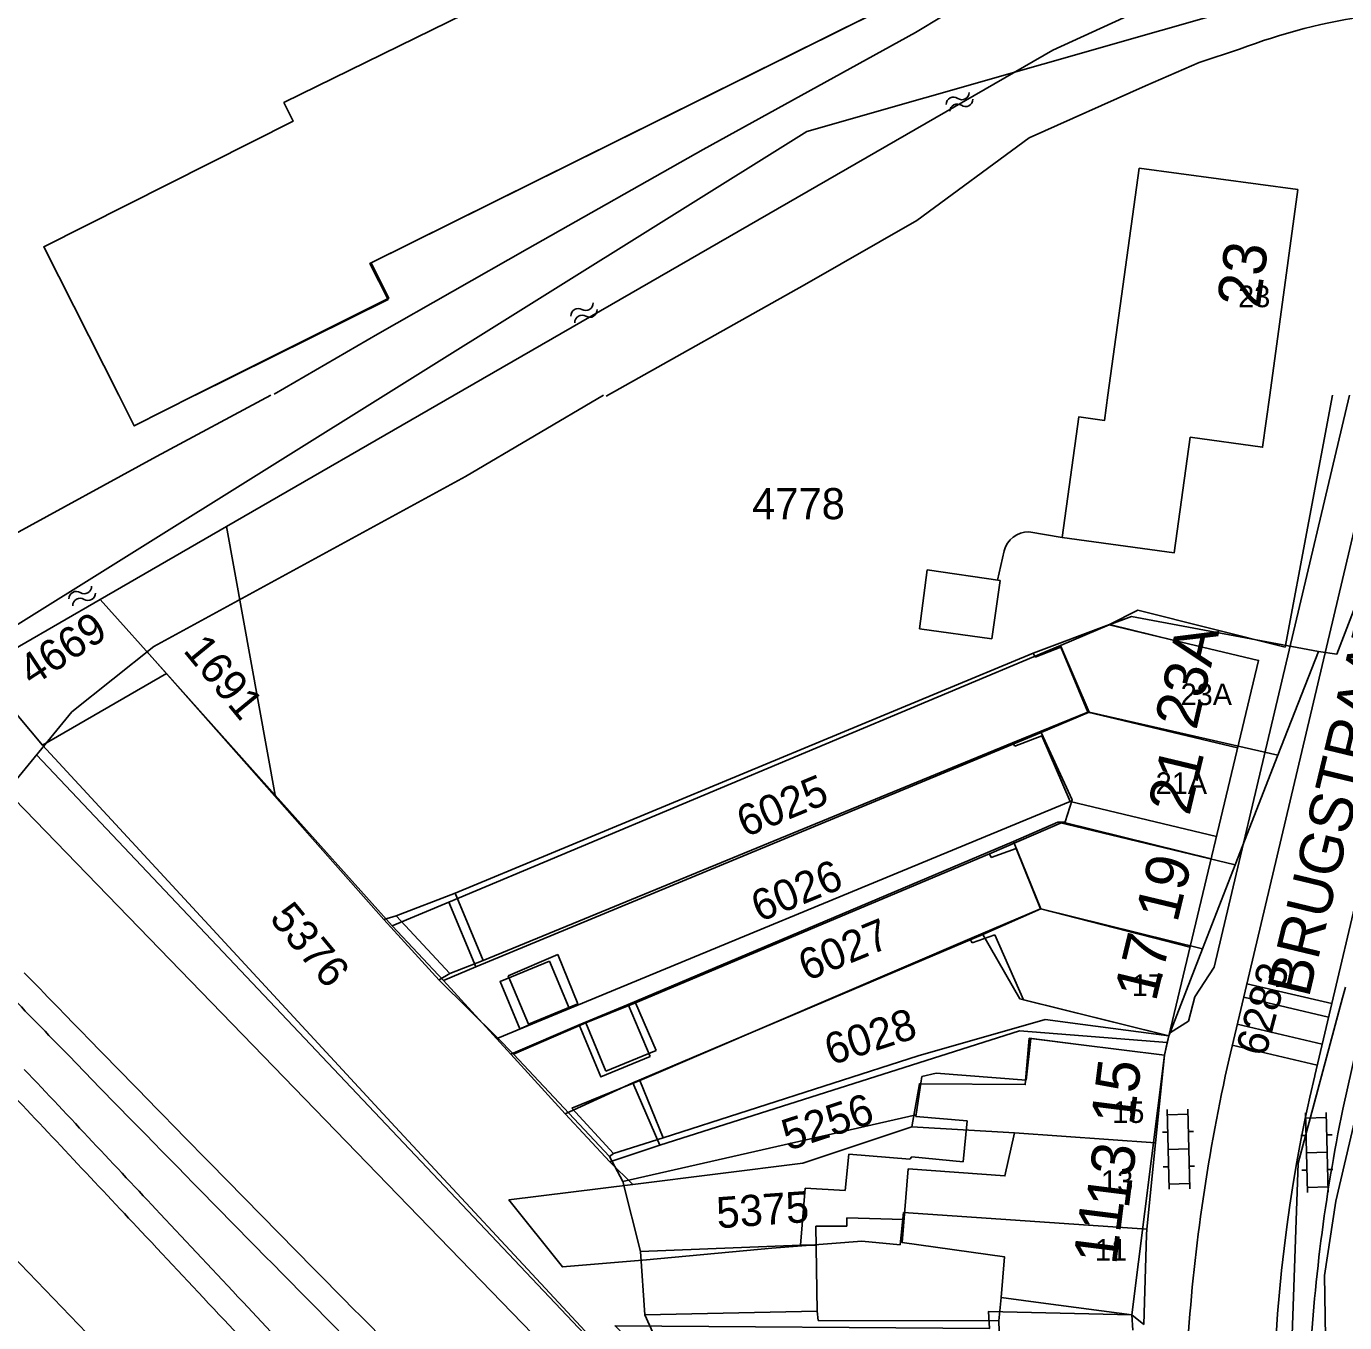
# Model space of a CAD drawing. Extents: x 148816 to 151297, y 399515 to 402500.
# Drawn here: x 149846 to 149922.2, y 399946.4 to 400021.3 of the extents above; entities that cross this region are included whole.
import ezdxf

# ---------------------------------------------------------------- set-up
doc = ezdxf.new("R2010")
doc.units = 0
for name, color, linetype in [('B01 Hoofdgebouw  [D] Norm', 7, 'Continuous'), ('B01 Hoofdgebouw  [T] Norm', 7, 'Continuous'), ('B01 hoofgebouw', 7, 'Continuous'), ('B02 Bijgebouw  [D] Norm', 7, 'Continuous'), ('B02 Bijgebouw  [T] Norm', 7, 'Continuous'), ('B07 Tussenmuur  [D] Norm', 7, 'Continuous'), ('G01 perceelsgrens', 7, 'Continuous'), ('G02 sectiegrens', 7, 'Continuous'), ('Q01 Spoorrail  [D] Norm', 7, 'Continuous'), ('Q21 Lichtmast  Gem', 7, 'Continuous'), ('S02 Open verharding  Norm', 7, 'Continuous'), ('S05 Water  Norm', 7, 'Continuous'), ('T04 Haag heg  [D] Gem', 7, 'Continuous'), ('T09 Insteek water  [T] Norm', 7, 'Continuous'), ('V00 Kant verharding algemeen  [T] Norm', 7, 'Continuous'), ('Z01 perceelnummer', 7, 'Continuous'), ('Z02 huisnummer', 7, 'Continuous'), ('Z02 Huisnummer  [Tekst] Norm', 7, 'Continuous'), ('Z06 straatnaam', 7, 'Continuous')]:
    doc.layers.add(name, color=color, linetype=linetype)

msp = doc.modelspace()

# ---------------------------------------------------------------- linework, layer by layer
at = {"layer": 'B01 Hoofdgebouw  [D] Norm'}
for p, q in [((149902.132, 399989.308), (149902.517, 399991.014)), ((149898.07, 399989.917), (149897.615, 399986.509)), ((149902.289, 399989.285), (149898.07, 399989.917)), ((149901.808, 399985.927), (149902.289, 399989.285)), ((149902.289, 399989.285), (149902.289, 399989.285)), ((149897.615, 399986.509), (149901.808, 399985.927)), ((149908.593, 399986.747), (149904.198, 399985.09)), ((149912.35, 399985.83), (149908.593, 399986.747)), ((149904.198, 399985.09), (149904.299, 399984.861)), ((149904.299, 399984.861), (149905.798, 399985.448)), ((149905.798, 399985.448), (149907.351, 399981.685)), ((149907.351, 399981.685), (149903.006, 399979.901)), ((149903.133, 399979.723), (149904.683, 399980.309)), ((149904.683, 399980.309), (149906.337, 399976.521)), ((149903.006, 399979.901), (149903.133, 399979.723)), ((149906.337, 399976.521), (149914.778, 399974.5)), ((149905.906, 399975.326), (149901.663, 399973.491)), ((149914.468, 399973.204), (149905.906, 399975.326)), ((149901.663, 399973.491), (149901.765, 399973.287)), ((149901.765, 399973.287), (149903.213, 399973.797)), ((149903.213, 399973.797), (149904.612, 399970.314)), ((149904.612, 399970.314), (149900.522, 399968.581)), ((149900.522, 399968.581), (149900.675, 399968.353)), ((149900.675, 399968.353), (149901.97, 399968.811)), ((149901.97, 399968.811), (149903.624, 399965.049)), ((149903.624, 399965.049), (149912.02, 399962.97)), ((149904.058, 399962.824), (149903.779, 399960.42)), ((149906.81, 399962.48), (149904.058, 399962.824)), ((149897.757, 399960.619), (149897.402, 399958.304)), ((149898.595, 399960.823), (149897.757, 399960.619)), ((149903.779, 399960.42), (149898.595, 399960.823)), ((149897.402, 399958.304), (149900.375, 399958.052)), ((149900.375, 399958.052), (149900.148, 399955.687)), ((149893.541, 399956.139), (149893.338, 399954.028)), ((149897.073, 399955.837), (149893.541, 399956.139)), ((149897.175, 399955.989), (149897.073, 399955.837)), ((149900.148, 399955.687), (149897.175, 399955.989)), ((149891.026, 399954.178), (149890.748, 399950.872)), ((149893.338, 399954.028), (149891.026, 399954.178)), ((149893.416, 399951.968), (149893.416, 399952.451)), ((149893.416, 399952.451), (149896.694, 399952.352)), ((149896.694, 399952.352), (149896.618, 399951.03)), ((149891.637, 399951.966), (149893.416, 399951.968)), ((149891.716, 399947.058), (149891.637, 399951.966)), ((149890.748, 399950.872), (149881.498, 399950.508)), ((149890.748, 399950.872), (149891.655, 399950.872)), ((149896.618, 399951.03), (149902.54, 399950.195)), ((149881.498, 399950.508), (149881.754, 399946.846)), ((149902.54, 399950.195), (149902.333, 399947.856)), ((149902.333, 399947.856), (149904.93, 399947.51)), ((149881.754, 399946.846), (149891.716, 399947.058))]:
    msp.add_line(p, q, dxfattribs=at)
msp.add_lwpolyline([(149902.04, 400025.57), (149865.869, 400007.623), (149866.921, 400005.543), (149855.774, 400000)], dxfattribs=at)
at = {"layer": 'B01 Hoofdgebouw  [T] Norm'}
for p, q in [((149860.9, 400016.92), (149872.29, 400022.52)), ((149861.44, 400015.85), (149860.9, 400016.92)), ((149847.03, 400008.59), (149861.44, 400015.85)), ((149908.51, 400000), (149910.32, 400013.13)), ((149910.32, 400013.13), (149919.48, 400011.89)), ((149919.48, 400011.89), (149917.86, 400000)), ((149851.36, 400000), (149847.03, 400008.59)), ((149852.25, 399998.23), (149851.36, 400000)), ((149855.76, 400000), (149852.25, 399998.23)), ((149908.31, 399998.54), (149908.51, 400000)), ((149917.86, 400000), (149917.45, 399997)), ((149905.87, 399991.77), (149906.82, 399998.75)), ((149906.82, 399998.75), (149908.31, 399998.54)), ((149913.27, 399997.57), (149912.33, 399990.89)), ((149917.45, 399997), (149913.27, 399997.57)), ((149912.33, 399990.89), (149905.87, 399991.77)), ((149917.21, 399984.67), (149912.35, 399985.83)), ((149912.02, 399962.97), (149917.21, 399984.67)), ((149907.06, 399963.63), (149912.02, 399962.97)), ((149911.77, 399961.86), (149906.81, 399962.48)), ((149909.89, 399946.85), (149911.77, 399961.86)), ((149904.93, 399947.51), (149909.89, 399946.85))]:
    msp.add_line(p, q, dxfattribs=at)
at = {"layer": 'B01 hoofgebouw'}
for points in [[(149851.358, 400000), (149847.03, 400008.59), (149861.44, 400015.85), (149860.9, 400016.92), (149872.29, 400022.52), (149871.67, 400023.72), (149888.44, 400031.92), (149889.24, 400030.29), (149892.42, 400031.84), (149892.98, 400030.69), (149897.14, 400032.69), (149882.15, 400055.29), (149894.61, 400057.99), (149911.2, 400033.26), (149907.93, 400031.05), (149909.5, 400028.73), (149902.76, 400024.2), (149902.04, 400025.57)], [(149856.71, 400000.48), (149866.96, 400005.61), (149865.94, 400007.66), (149901.89, 400025.52)], [(149908.511, 400000), (149910.32, 400013.13)], [(149910.32, 400013.13), (149919.48, 400011.89), (149917.859, 400000)], [(149856.71, 400000.48), (149855.759, 400000)], [(149855.759, 400000), (149852.25, 399998.23), (149851.358, 400000)], [(149917.859, 400000), (149917.45, 399997), (149913.27, 399997.57), (149912.33, 399990.89), (149905.87, 399991.77), (149906.82, 399998.75), (149908.31, 399998.54), (149908.511, 400000)], [(149912.35, 399985.83), (149908.591, 399986.727), (149905.771, 399985.535), (149907.432, 399981.679), (149904.653, 399980.504), (149906.438, 399976.622), (149906.035, 399975.341), (149905.608, 399975.329), (149903.047, 399974.202), (149904.633, 399970.312), (149901.282, 399968.826), (149903.425, 399965.106), (149912.02, 399962.97)], [(149907.06, 399963.63), (149912.02, 399962.97), (149917.21, 399984.67), (149912.35, 399985.83)], [(149870.433, 399970.695), (149871.992, 399966.967), (149870.114, 399966.182), (149867.157, 399969.325), (149870.433, 399970.695)], [(149876.238, 399967.294), (149877.373, 399964.569), (149874.527, 399963.384), (149873.392, 399966.109), (149876.238, 399967.294)], [(149882.054, 399961.784), (149879.221, 399960.603), (149877.967, 399963.608), (149880.8, 399964.79), (149882.054, 399961.784)], [(149904.93, 399947.51), (149902.333, 399947.856), (149902.54, 399950.195), (149896.618, 399951.03), (149896.978, 399955.283), (149902.563, 399954.873), (149903.107, 399957.376), (149897.189, 399957.721), (149897.617, 399960.207), (149903.736, 399960.154), (149903.962, 399962.836), (149906.81, 399962.48)], [(149904.93, 399947.51), (149909.89, 399946.85), (149911.77, 399961.86), (149906.81, 399962.48)], [(149881.054, 399960.253), (149882.628, 399956.662), (149879.729, 399955.698), (149877.146, 399958.47), (149881.054, 399960.253)], [(149909.95, 399945.97), (149909.89, 399946.85)]]:
    msp.add_lwpolyline(points, dxfattribs=at)
at = {"layer": 'B02 Bijgebouw  [D] Norm'}
for p, q in [((149905.87, 399991.77), (149903.94, 399992.109)), ((149870.788, 399971.226), (149867.384, 399969.901)), ((149872.417, 399967.336), (149870.788, 399971.226)), ((149867.384, 399969.901), (149870.486, 399966.572)), ((149867.384, 399969.901), (149867.384, 399969.901)), ((149870.486, 399966.572), (149872.417, 399967.336)), ((149876.737, 399967.671), (149873.866, 399966.447)), ((149877.882, 399964.823), (149876.737, 399967.671)), ((149876.737, 399967.671), (149876.737, 399967.671)), ((149873.866, 399966.447), (149875.036, 399963.651)), ((149875.036, 399963.651), (149877.882, 399964.823)), ((149881.211, 399964.877), (149878.34, 399963.73)), ((149882.407, 399962.131), (149881.211, 399964.877)), ((149881.211, 399964.877), (149881.211, 399964.877)), ((149878.34, 399963.73), (149879.51, 399960.933)), ((149879.51, 399960.933), (149882.407, 399962.131)), ((149881.467, 399960.401), (149877.529, 399958.795)), ((149882.816, 399957.071), (149881.467, 399960.401)), ((149877.529, 399958.795), (149879.945, 399956.178)), ((149877.529, 399958.795), (149877.529, 399958.795)), ((149879.945, 399956.178), (149882.816, 399957.071))]:
    msp.add_line(p, q, dxfattribs=at)
msp.add_arc((149903.931, 399990.649), 1.46, 89.62838, 165.52826, dxfattribs=at)
at = {"layer": 'B02 Bijgebouw  [T] Norm'}
msp.add_line((149909.95, 399945.97), (149909.89, 399946.85), dxfattribs=at)
at = {"layer": 'B07 Tussenmuur  [D] Norm'}
for p, q in [((149907.351, 399981.685), (149916.004, 399979.626)), ((149907.351, 399981.685), (149916.004, 399979.626)), ((149904.612, 399970.314), (149913.247, 399968.102)), ((149904.612, 399970.314), (149913.247, 399968.102))]:
    msp.add_line(p, q, dxfattribs=at)
at = {"layer": 'G01 perceelsgrens'}
for points in [[(149927.878, 400000), (149925.915, 399995.894), (149921.732, 399985.026), (149920.67, 399985.193)], [(149857.58, 399992.406), (149860.389, 399976.895)], [(149850.284, 399988.197), (149854.11, 399983.918)], [(149920.67, 399985.193), (149909.867, 399987.213), (149908.591, 399986.727), (149905.771, 399985.535), (149870.433, 399970.695), (149867.157, 399969.325)], [(149920.67, 399985.193), (149918.333, 399979.189)], [(149854.11, 399983.918), (149846.947, 399979.77)], [(149854.11, 399983.918), (149860.389, 399976.895)], [(149930.008, 399890.234), (149895.044, 399925.331), (149839.926, 399982.22)], [(149918.333, 399979.189), (149907.432, 399981.679), (149904.653, 399980.504), (149871.992, 399966.967), (149870.114, 399966.182)], [(149918.333, 399979.189), (149915.87, 399972.862)], [(149860.389, 399976.895), (149867.157, 399969.325)], [(149915.87, 399972.862), (149905.608, 399975.329), (149903.047, 399974.202), (149880.8, 399964.79), (149877.967, 399963.608), (149874.012, 399961.907)], [(149915.87, 399972.862), (149913.982, 399968.011)], [(149824.935, 399971.333), (149852.884, 399942.282), (149864.818, 399929.5), (149871.974, 399921.819), (149900.742, 399890.705), (149870.334, 399913.557), (149853.477, 399925.258), (149834.506, 399937.866), (149821.784, 399945.874), (149804.582, 399956.252), (149802.467, 399957.457)], [(149913.982, 399968.011), (149904.633, 399970.312), (149901.282, 399968.826), (149881.054, 399960.253), (149877.146, 399958.47)], [(149867.157, 399969.325), (149870.114, 399966.182)], [(149913.982, 399968.011), (149912.02, 399962.97), (149911.933, 399962.584)], [(149870.114, 399966.182), (149874.012, 399961.907)], [(149922.9, 399909.563), (149921.399, 399911.255), (149918.52, 399927.748), (149918.826, 399936.319), (149919.492, 399955.614), (149922.06, 399965.172), (149922.242, 399965.791)], [(149911.933, 399962.584), (149903.404, 399963.259), (149882.628, 399956.662), (149879.729, 399955.698)], [(149911.933, 399962.584), (149911.77, 399961.86), (149911.264, 399956.782)], [(149874.012, 399961.907), (149877.146, 399958.47)], [(149877.146, 399958.47), (149879.729, 399955.698)], [(149881.059, 399954.386), (149890.889, 399955.618), (149897.189, 399957.721), (149903.107, 399957.376), (149911.264, 399956.782)], [(149911.264, 399956.782), (149910.767, 399951.791)], [(149879.729, 399955.698), (149881.059, 399954.386)], [(149910.767, 399951.791), (149896.702, 399952.756), (149896.498, 399950.897), (149894.299, 399951.097), (149889.086, 399950.701), (149881.855, 399950.032), (149876.995, 399949.613), (149873.901, 399953.489), (149881.059, 399954.386)], [(149910.767, 399951.791), (149910.735, 399951.464), (149910.579, 399946.283)], [(149910.579, 399946.283), (149909.89, 399946.85), (149901.608, 399947.039), (149901.662, 399946.052), (149880.038, 399946.211), (149887.147, 399938.873)]]:
    msp.add_lwpolyline(points, dxfattribs=at)
at = {"layer": 'G02 sectiegrens'}
for points in [[(149870.742, 400000), (149905.32, 400019.95), (149922.13, 400027.66)], [(149857.58, 399992.406), (149870.742, 400000)], [(149850.284, 399988.197), (149857.58, 399992.406)], [(149843.27, 399984.15), (149850.284, 399988.197)], [(149846.947, 399979.77), (149843.27, 399984.15)], [(149913.331, 399909.161), (149910.53, 399911.262), (149898.704, 399923.966), (149867.334, 399957.713), (149846.947, 399979.77)]]:
    msp.add_lwpolyline(points, dxfattribs=at)
at = {"layer": 'Q01 Spoorrail  [D] Norm'}
for points in [[(149849.543, 399962.876), (149851.369, 399961.003), (149853.196, 399959.131)], [(149848.469, 399961.828), (149850.295, 399959.955), (149852.122, 399958.083)], [(149858.542, 399947.576), (149860.933, 399945.02), (149863.323, 399942.462)], [(149857.446, 399946.552), (149859.837, 399943.996), (149862.227, 399941.438)]]:
    msp.add_lwpolyline(points, dxfattribs=at)
for centre, radius, start, end in [((149374.899, 399222.566), 839.824, 47.976611, 67.901486), ((149374.91, 399222.59), 843.799, 50.163417, 67.241111), ((149374.899, 399222.566), 838.324, 47.976611, 67.901486), ((149374.91, 399222.59), 842.299, 50.163417, 67.241111), ((152511.996, 402554.543), 3715.561, 224.147506, 224.228153), ((152511.996, 402554.543), 3717.061, 224.147506, 224.228153), ((146203.865, 396528.628), 5004.585, 43.171467, 43.302697), ((146203.865, 396528.628), 5003.085, 43.171467, 43.302697), ((151370.578, 401440.04), 2120.269, 224.30305, 224.44435), ((151370.578, 401440.04), 2121.769, 224.30305, 224.44435), ((151998.933, 402054.677), 2999.25, 224.421886, 225.295789), ((151998.933, 402054.677), 3000.75, 224.421886, 225.295789), ((147497.058, 397739.75), 3232.817, 43.07395, 43.198039), ((147497.058, 397739.75), 3231.317, 43.07395, 43.198039)]:
    msp.add_arc(centre, radius, start, end, dxfattribs=at)
at = {"layer": 'Q21 Lichtmast  Gem'}
msp.add_lwpolyline([(150470.017, 401545.896), (150556.482, 401148.679), (150587.331, 401006.961), (150639.146, 400861.228), (150791.995, 400651.605), (150911.823, 400487.271), (150967.929, 400385.834), (150992.884, 400314.712), (150864.365, 400354.64), (150785.757, 400358.383), (150705.901, 400348.401), (150564.281, 400314.712), (150489.416, 400271.041), (150319.721, 400151.257), (150222.396, 400100.099), (150103.263, 400037.477), (150071.606, 400097.702), (150036.481, 400058.923), (149995.306, 400040.207), (149954.13, 400021.49), (149930.422, 400026.481), (149891.118, 400015.252), (149831.226, 399977.819), (149652.797, 400166.23)], dxfattribs=at)
at = {"layer": 'S02 Open verharding  Norm'}
for p, q in [((149911.931, 399958.708), (149912.039, 399954.109)), ((149911.938, 399958.408), (149913.138, 399958.437)), ((149913.131, 399958.737), (149913.239, 399954.138)), ((149919.927, 399958.515), (149920.035, 399953.916)), ((149919.934, 399958.215), (149921.134, 399958.244)), ((149921.127, 399958.544), (149921.235, 399953.945)), ((149911.962, 399957.409), (149911.662, 399957.401)), ((149913.461, 399957.444), (149913.161, 399957.437)), ((149919.958, 399957.216), (149919.658, 399957.208)), ((149921.457, 399957.251), (149921.157, 399957.244)), ((149913.185, 399956.437), (149911.985, 399956.409)), ((149921.181, 399956.244), (149919.981, 399956.216)), ((149912.009, 399955.409), (149911.709, 399955.402)), ((149913.508, 399955.445), (149913.208, 399955.437)), ((149920.005, 399955.216), (149919.705, 399955.209)), ((149921.504, 399955.252), (149921.204, 399955.244)), ((149912.032, 399954.409), (149913.232, 399954.438)), ((149920.028, 399954.216), (149921.228, 399954.245))]:
    msp.add_line(p, q, dxfattribs=at)
at = {"layer": 'S05 Water  Norm'}
for centre, start, end in [((149899.593, 400016.809), 55.5755, 179.43053), ((149899.801, 400016.41), 55.5755, 179.43053), ((149900.073, 400017.51), 235.57551, 359.43053), ((149900.281, 400017.111), 235.57551, 359.43053), ((149877.903, 400004.595), 58.84095, 182.69598), ((149878.133, 400004.208), 58.84095, 182.69598), ((149878.343, 400005.322), 238.84095, 2.69598), ((149878.573, 400004.935), 238.84095, 2.69598), ((149848.906, 399988.237), 57.40229, 181.25731), ((149849.364, 399988.953), 237.40228, 1.2573), ((149849.126, 399987.845), 57.40229, 181.25731), ((149849.584, 399988.561), 237.40228, 1.2573)]:
    msp.add_arc(centre, 0.425, start, end, dxfattribs=at)
at = {"layer": 'T04 Haag heg  [D] Gem'}
for p, q in [((149921.48, 400000), (149918.749, 399985.432)), ((149908.593, 399986.747), (149910.244, 399987.588)), ((149910.244, 399987.588), (149918.749, 399985.432)), ((149853.006, 399985.166), (149866.672, 399969.697)), ((149904.198, 399985.09), (149870.788, 399971.226)), ((149872.417, 399967.336), (149903.006, 399979.901)), ((149846.607, 399979.219), (149889.106, 399934.289)), ((149906.337, 399976.521), (149873.258, 399962.835)), ((149901.663, 399973.491), (149881.211, 399964.877)), ((149867.384, 399969.901), (149866.672, 399969.697)), ((149866.672, 399969.697), (149869.876, 399966.19)), ((149900.522, 399968.581), (149881.467, 399960.401)), ((149870.486, 399966.572), (149869.876, 399966.215)), ((149869.876, 399966.19), (149873.258, 399962.835)), ((149878.34, 399963.73), (149874.173, 399961.921)), ((149897.553, 399961.814), (149904.892, 399963.919)), ((149904.892, 399963.919), (149907.06, 399963.63)), ((149873.258, 399962.835), (149874.173, 399961.921)), ((149912.02, 399962.97), (149911.77, 399961.86)), ((149874.173, 399961.921), (149879.716, 399956)), ((149882.816, 399957.071), (149897.553, 399961.814)), ((149880.48, 399954.551), (149897.427, 399958.406)), ((149879.716, 399956), (149879.945, 399956.178)), ((149879.716, 399956), (149879.716, 399956)), ((149879.716, 399956), (149880.48, 399954.551)), ((149880.48, 399954.551), (149881.498, 399950.508)), ((149902.333, 399947.856), (149902.212, 399946.508)), ((149881.754, 399946.846), (149882.289, 399945.651)), ((149891.716, 399947.058), (149891.767, 399946.524)), ((149891.767, 399946.524), (149902.212, 399946.508)), ((149902.212, 399946.508), (149902.238, 399945.312))]:
    msp.add_line(p, q, dxfattribs=at)
at = {"layer": 'T09 Insteek water  [T] Norm'}
for p, q in [((149916.11, 400020), (149913.78, 400019.24)), ((149913.78, 400019.24), (149910.69, 400017.88)), ((149910.69, 400017.88), (149903.95, 400014.89)), ((149860.153, 400000), (149853.54, 399996.47)), ((149879.366, 400000), (149871.385, 399995.311)), ((149845.16, 399991.87), (149853.54, 399996.47)), ((149871.385, 399995.311), (149853.39, 399985.47)), ((149848.64, 399981.71), (149853.39, 399985.47)), ((149844.73, 399976.92), (149848.64, 399981.71))]:
    msp.add_line(p, q, dxfattribs=at)
for points in [[(149902.19, 400023.88), (149897.398, 400020.975), (149885.126, 400014.209), (149874.984, 400008.46), (149866.312, 400003.526), (149860.329, 400000.067)], [(149903.95, 400014.89), (149897.466, 400010.095), (149890.976, 400006.381), (149879.515, 399999.946)]]:
    msp.add_lwpolyline(points, dxfattribs=at)
msp.add_arc((149928.3, 399988.298), 33.965, 97.7841, 111.03315, dxfattribs=at)
at = {"layer": 'V00 Kant verharding algemeen  [T] Norm'}
for p, q in [((149922.47, 400000), (149914.65, 399966.94)), ((149915.51, 399961.64), (149924.57, 400000)), ((149929.73, 400000), (149920.46, 399960.68)), ((149914.65, 399966.94), (149913.53, 399965.23)), ((149923.91, 399966.94), (149922.08, 399958.73)), ((149913.53, 399965.23), (149913.16, 399963.83)), ((149924.411, 399965.143), (149921.674, 399953.417)), ((149913.16, 399963.83), (149912.12, 399963.16)), ((149921.674, 399953.417), (149921.015, 399949.118)), ((149921.015, 399949.118), (149921.08, 399945.56))]:
    msp.add_line(p, q, dxfattribs=at)
for points in [[(149921.44, 399964.837), (149916.537, 399965.988)], [(149921.256, 399964.058), (149916.353, 399965.209)], [(149920.889, 399962.5), (149915.985, 399963.652)], [(149920.602, 399961.283), (149915.694, 399962.436)]]:
    msp.add_lwpolyline(points, dxfattribs=at)
for centre, radius, start, end in [((150019.621, 399938.101), 106.738, 167.2601, 176.09531), ((150006.85, 399940.161), 88.791, 166.64541, 192.81299), ((150021.722, 399938.313), 101.713, 168.41996, 177.09916)]:
    msp.add_arc(centre, radius, start, end, dxfattribs=at)

# ---------------------------------------------------------------- texts
at = {"layer": 'Z01 perceelnummer'}
msp.add_text('4778', height=1.8, dxfattribs=at).set_placement((149887.957, 399992.837))
for s, rotation, p in [('4669', 33.35341, (149846.354, 399983.135)), ('1691', 309.42584, (149855.034, 399985.231)), ('6025', 22.47759, (149887.552, 399974.426)), ('6026', 22.25145, (149888.376, 399969.529)), ('5376', 309.67426, (149860.013, 399969.746)), ('6027', 22.41149, (149891.109, 399966.113)), ('6283', 75.15051, (149917.613, 399961.715)), ('6028', 17.90865, (149892.502, 399961.259)), ('5256', 18.08793, (149890.029, 399956.321)), ('5375', 4.02826, (149885.952, 399951.843))]:
    msp.add_text(s, height=1.8, rotation=rotation, dxfattribs=at).set_placement(p)
at = {"layer": 'Z02 huisnummer'}
for s, rotation, p in [('23', 82.24257, (149917.277, 400004.982)), ('23A', 76.88086, (149913.612, 399980.595)), ('21', 76.53322, (149913.214, 399975.65)), ('19', 76.53322, (149912.514, 399969.455)), ('17', 76.53322, (149911.272, 399964.891)), ('15', 82.87498, (149909.993, 399957.744)), ('13', 82.87498, (149909.71, 399952.925)), ('11', 82.87498, (149908.985, 399949.688))]:
    msp.add_text(s, height=2.5, rotation=rotation, dxfattribs=at).set_placement(p)
at = {"layer": 'Z02 Huisnummer  [Tekst] Norm'}
for s, height, p in [('23', 1.25, (149916.03, 400005.09)), ('23A', 1.249, (149912.709, 399982.088)), ('21A', 1.249, (149911.267, 399976.957)), ('17', 1.249, (149909.89, 399965.283)), ('15', 1.249, (149908.76, 399957.94)), ('13', 1.249, (149908.112, 399953.947)), ('11', 1.249, (149907.76, 399949.98))]:
    msp.add_text(s, height=height, dxfattribs=at).set_placement(p)
at = {"layer": 'Z06 straatnaam'}
msp.add_text('BRUGSTRAAT', height=2.5, rotation=76.46414, dxfattribs=at).set_placement((149920.113, 399965.125))

doc.saveas('drawing.dxf')
